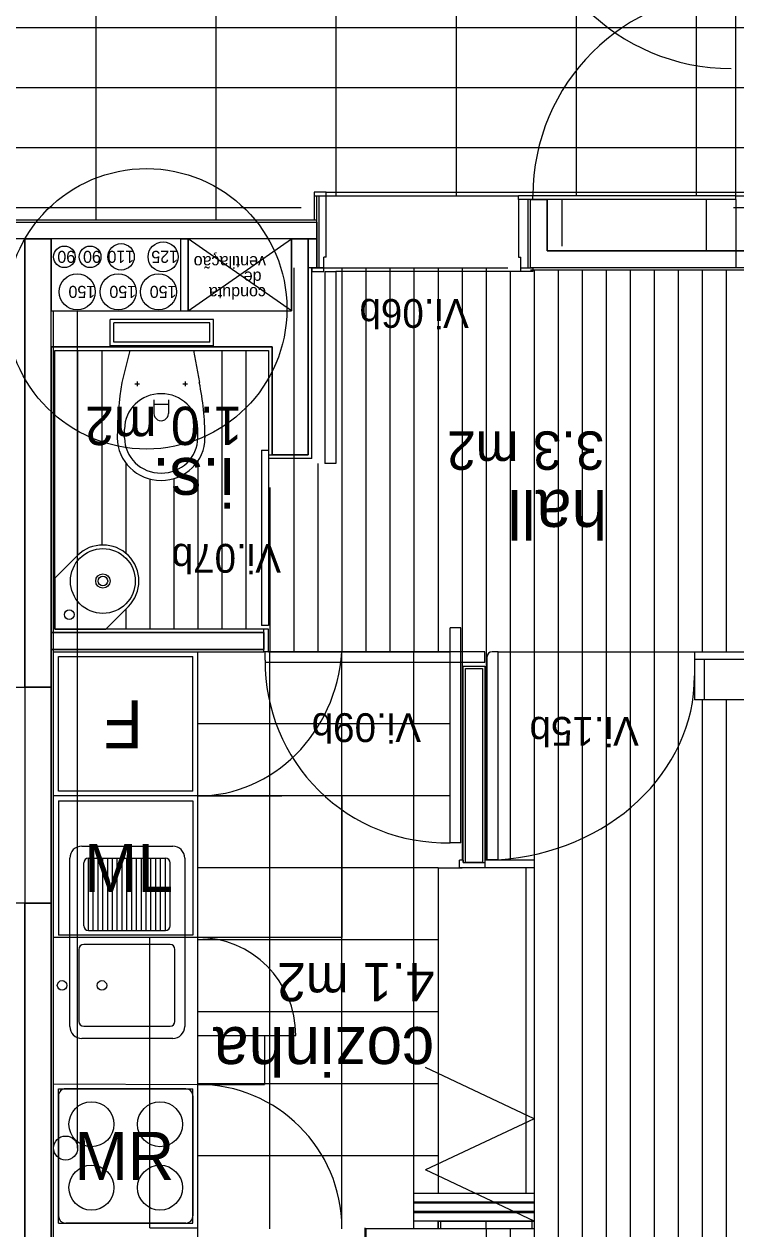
# Model space of a CAD drawing. Extents: x 1248 to 1356, y -443 to -224.
# Drawn here: x 1334.72 to 1337.68, y -244.43 to -239.41 of the extents above; entities that cross this region are included whole.
import ezdxf

# ---------------------------------------------------------------- set-up
doc = ezdxf.new("R2010")
doc.units = 0
for name, color, linetype in [('corte', 7, 'Continuous'), ('estereoctomias', 7, 'Continuous'), ('ind-pormenores', 7, 'Continuous'), ('Level 1', 7, 'Continuous'), ('Level 10', 7, 'Continuous'), ('Level 11', 7, 'Continuous'), ('Level 13', 7, 'Continuous'), ('Level 2', 7, 'Continuous'), ('Level 3', 7, 'Continuous'), ('Level 31', 7, 'Continuous'), ('Level 4', 7, 'Continuous'), ('Level 40', 7, 'Continuous'), ('Level 41', 7, 'Continuous'), ('Level 60', 7, 'Continuous'), ('mob-fixo', 7, 'Continuous'), ('revestimentos', 7, 'Continuous')]:
    doc.layers.add(name, color=color, linetype=linetype)

msp = doc.modelspace()

# ---------------------------------------------------------------- linework, layer by layer
at = {"layer": 'corte'}
for p, q in [((1335.8333, -240.304), (1332.3825, -240.304)), ((1335.3733, -240.604), (1335.3733, -240.304)), ((1335.4033, -240.604), (1335.4033, -240.304)), ((1335.8333, -240.304), (1335.8333, -240.604)), ((1335.9383, -240.304), (1335.9033, -240.304)), ((1337.7283, -240.354), (1336.8983, -240.354)), ((1340.0033, -240.424), (1336.8283, -240.424)), ((1334.8333, -240.754), (1335.7533, -240.754)), ((1336.5483, -242.892), (1336.5483, -242.902)), ((1336.6383, -242.892), (1336.6383, -242.924))]:
    msp.add_line(p, q, dxfattribs=at)
msp.add_lwpolyline([(1334.8325, -243.0713), (1334.6025, -243.0713), (1334.6025, -242.1713), (1334.8325, -242.1713)], close=True, dxfattribs=at)
at = {"layer": 'estereoctomias'}
msp.add_line((1335.9783, -240.124), (1336.7783, -240.124), dxfattribs=at)
for points in [[(1340.0033, -242.1713), (1340.0033, -240.424), (1336.8283, -240.424), (1336.8283, -240.139), (1336.8983, -240.139), (1336.8983, -240.354), (1340.0733, -240.354), (1340.0733, -242.1717)], [(1335.9383, -240.234), (1335.9383, -240.304), (1332.3825, -240.304), (1332.3825, -240.354), (1332.3125, -240.354), (1332.3125, -240.234)], [(1335.9033, -240.304), (1335.9033, -241.204), (1335.7533, -241.204), (1335.7533, -240.754), (1334.8333, -240.754), (1334.8333, -242.1713), (1334.7233, -242.1713), (1334.7233, -240.304), (1334.8333, -240.304), (1334.8333, -240.604), (1335.3733, -240.604), (1335.3733, -240.304), (1335.4033, -240.304), (1335.4033, -240.604), (1335.8333, -240.604), (1335.8333, -240.304)], [(1335.9383, -240.424), (1335.9033, -240.424), (1335.9033, -240.314), (1335.9033, -240.304), (1335.9383, -240.304), (1335.9383, -240.314)], [(1335.7183, -241.944), (1335.7183, -242.014), (1334.8333, -242.014), (1334.8333, -241.944)], [(1336.6283, -242.094), (1336.6283, -242.902), (1336.5583, -242.902), (1336.5583, -242.094)], [(1334.8325, -245.8713), (1334.7233, -245.8713), (1334.7233, -243.0713), (1334.8333, -243.0713), (1334.8333, -245.8713)], [(1336.8433, -244.3959), (1336.8433, -244.4279), (1336.4433, -244.4279), (1336.4433, -244.3959)]]:
    msp.add_lwpolyline(points, close=True, dxfattribs=at)
at = {"layer": 'ind-pormenores'}
msp.add_circle((1335.2301, -240.5951), 0.5842, dxfattribs=at)
at = {"layer": 'Level 1'}
for p, q in [((1336.8983, -240.139), (1336.8283, -240.139)), ((1336.8283, -240.424), (1336.8283, -240.139)), ((1336.8983, -240.354), (1336.8983, -240.139)), ((1332.3125, -240.234), (1335.9383, -240.234)), ((1335.9383, -240.424), (1335.9383, -240.234)), ((1334.7233, -240.304), (1334.7233, -246.734)), ((1334.8333, -241.934), (1334.8333, -240.304)), ((1335.9033, -241.204), (1335.9033, -240.304)), ((1335.9383, -240.424), (1335.9033, -240.424)), ((1334.8333, -240.604), (1335.8333, -240.604)), ((1335.7533, -240.754), (1335.7533, -241.204)), ((1335.7383, -241.204), (1335.9033, -241.204)), ((1334.8333, -246.584), (1334.8333, -241.934)), ((1335.7183, -241.944), (1334.8333, -241.944)), ((1335.7183, -242.024), (1335.7183, -241.929)), ((1334.8333, -242.014), (1335.7183, -242.014)), ((1336.5583, -242.902), (1336.5583, -242.094)), ((1336.5583, -242.094), (1336.6283, -242.094)), ((1336.6283, -242.094), (1336.6283, -242.902)), ((1336.5483, -242.892), (1336.5333, -242.892)), ((1336.5333, -242.924), (1336.5333, -242.892)), ((1336.5483, -242.902), (1336.6383, -242.902)), ((1336.8433, -242.892), (1336.6383, -242.892)), ((1336.8433, -242.892), (1336.8433, -242.924)), ((1336.8433, -242.924), (1336.5333, -242.924)), ((1336.4433, -244.3959), (1336.4433, -244.424)), ((1336.8433, -244.3959), (1336.4433, -244.3959)), ((1336.4433, -244.3959), (1336.4433, -244.4279)), ((1336.4533, -244.3959), (1336.4533, -244.4279)), ((1336.6433, -244.4279), (1336.6433, -244.3959)), ((1336.8333, -244.3959), (1336.8333, -244.4279)), ((1336.8433, -244.3959), (1336.8433, -244.4279)), ((1336.8433, -244.4279), (1336.6433, -244.4279))]:
    msp.add_line(p, q, dxfattribs=at)
at = {"layer": 'Level 10'}
for p, q in [((1335.0183, -238.624), (1335.0183, -240.224)), ((1335.5183, -238.624), (1335.5183, -240.224)), ((1336.0183, -238.724), (1336.0183, -240.124)), ((1336.5183, -238.724), (1336.5183, -240.124)), ((1337.0183, -238.724), (1337.0183, -240.124)), ((1337.5183, -238.724), (1337.5183, -240.124)), ((1347.9933, -239.424), (1315.7633, -239.424)), ((1347.9933, -239.674), (1315.7633, -239.674)), ((1347.9933, -239.924), (1315.7633, -239.924)), ((1335.8733, -240.174), (1332.2725, -240.174)), ((1341.274, -240.174), (1337.6733, -240.174)), ((1335.8433, -240.424), (1335.8433, -242.024)), ((1335.9133, -240.424), (1336.7333, -240.424)), ((1336.0433, -240.424), (1336.0433, -242.024)), ((1336.1433, -240.424), (1336.1433, -242.024)), ((1336.2433, -240.424), (1336.2433, -242.024)), ((1336.3433, -240.424), (1336.3433, -242.024)), ((1336.4433, -240.424), (1336.4433, -242.024)), ((1336.5433, -240.424), (1336.5433, -242.892)), ((1336.6433, -240.424), (1336.6433, -242.892)), ((1336.7433, -240.439), (1336.7433, -242.892)), ((1336.8433, -240.434), (1336.8433, -242.892)), ((1336.9433, -240.434), (1336.9433, -246.574)), ((1337.0433, -240.434), (1337.0433, -246.574)), ((1337.1433, -240.434), (1337.1433, -246.574)), ((1337.2433, -240.434), (1337.2433, -246.574)), ((1337.3433, -240.434), (1337.3433, -246.574)), ((1337.4433, -240.434), (1337.4433, -246.574)), ((1337.5433, -240.434), (1337.5433, -242.024)), ((1337.6433, -240.434), (1337.6433, -242.024)), ((1334.9433, -240.769), (1334.9433, -241.6218)), ((1335.0433, -240.769), (1335.0433, -241.579)), ((1335.5433, -240.769), (1335.5433, -241.929)), ((1335.6433, -240.769), (1335.6433, -241.929)), ((1335.1433, -241.2366), (1335.1433, -241.6129)), ((1335.4433, -241.2297), (1335.4433, -241.929)), ((1335.9433, -241.239), (1335.9433, -242.024)), ((1335.2433, -241.3035), (1335.2433, -241.929)), ((1335.3433, -241.3022), (1335.3433, -241.929)), ((1335.7433, -241.339), (1335.7433, -242.024)), ((1335.1433, -241.8461), (1335.1433, -241.929)), ((1335.7383, -242.024), (1336.4933, -242.024)), ((1335.7433, -244.428), (1335.7433, -242.024)), ((1336.0433, -244.428), (1336.0433, -242.024)), ((1336.3433, -244.428), (1336.3433, -242.024)), ((1337.5433, -242.224), (1337.5433, -246.574)), ((1337.6433, -242.224), (1337.6433, -246.574)), ((1336.4933, -242.324), (1335.4433, -242.324)), ((1336.4933, -242.624), (1335.4433, -242.624)), ((1336.4933, -242.624), (1335.4433, -242.624)), ((1336.4433, -242.924), (1335.4433, -242.924)), ((1336.4433, -243.224), (1335.4433, -243.224)), ((1336.4433, -243.224), (1335.4433, -243.224)), ((1336.4433, -243.524), (1335.4433, -243.524)), ((1336.4433, -243.824), (1335.4433, -243.824)), ((1336.4433, -244.124), (1335.4433, -244.124)), ((1336.7433, -244.4279), (1336.7433, -246.574)), ((1336.8433, -244.4279), (1336.8433, -246.574))]:
    msp.add_line(p, q, dxfattribs=at)
at = {"layer": 'Level 11'}
for p, q in [((1335.0783, -240.749), (1335.0783, -240.639)), ((1335.5083, -240.639), (1335.0783, -240.639)), ((1335.4933, -240.654), (1335.0933, -240.654)), ((1335.0933, -240.734), (1335.0933, -240.654)), ((1335.4933, -240.734), (1335.4933, -240.654)), ((1335.5083, -240.749), (1335.5083, -240.639)), ((1335.5083, -240.749), (1335.0783, -240.749)), ((1335.4933, -240.734), (1335.0933, -240.734)), ((1335.1609, -240.769), (1335.1269, -240.9017)), ((1335.1609, -240.769), (1335.4256, -240.769)), ((1335.4256, -240.769), (1335.4498, -240.9017)), ((1335.1808, -240.9079), (1335.2008, -240.9079)), ((1335.1908, -240.8979), (1335.1908, -240.9179)), ((1335.3808, -240.9079), (1335.4008, -240.9079)), ((1335.3908, -240.8979), (1335.3908, -240.9179)), ((1335.2608, -240.9742), (1335.2608, -241.0313)), ((1335.2608, -240.9919), (1335.3208, -240.9919)), ((1335.3208, -240.9742), (1335.3208, -241.0314)), ((1335.1383, -241.1322), (1335.1383, -241.0961)), ((1335.4433, -241.1322), (1335.4433, -241.0961)), ((1335.1083, -241.1288), (1335.1083, -241.1325)), ((1335.4733, -241.1288), (1335.4733, -241.1325)), ((1334.9422, -241.6229), (1334.8483, -241.7168)), ((1334.8483, -241.7168), (1334.8483, -241.929)), ((1335.1543, -241.835), (1335.0604, -241.929)), ((1334.8483, -241.929), (1335.0604, -241.929)), ((1334.8633, -242.604), (1334.8633, -242.044)), ((1334.8633, -242.044), (1335.4233, -242.044)), ((1335.4233, -242.604), (1335.4233, -242.044)), ((1335.4233, -242.604), (1334.8633, -242.604)), ((1334.9684, -243.1651), (1334.9684, -242.9035)), ((1334.9884, -242.8835), (1335.3084, -242.8835)), ((1334.9884, -243.1851), (1334.9884, -242.8835)), ((1335.0084, -243.1851), (1335.0084, -242.8835)), ((1335.0284, -243.1851), (1335.0284, -242.8835)), ((1335.0484, -243.1851), (1335.0484, -242.8835)), ((1335.0684, -243.1851), (1335.0684, -242.8835)), ((1335.0884, -243.1851), (1335.0884, -242.8835)), ((1335.1084, -243.1851), (1335.1084, -242.8835)), ((1335.1284, -243.1851), (1335.1284, -242.8835)), ((1335.1484, -243.1851), (1335.1484, -242.8835)), ((1335.1684, -243.1851), (1335.1684, -242.8835)), ((1335.1884, -243.1851), (1335.1884, -242.8835)), ((1335.2084, -243.1851), (1335.2084, -242.8835)), ((1335.2284, -243.1851), (1335.2284, -242.8835)), ((1335.2484, -243.1851), (1335.2484, -242.8835)), ((1335.2684, -243.1851), (1335.2684, -242.8835)), ((1335.2884, -243.1851), (1335.2884, -242.8835)), ((1335.3084, -243.1851), (1335.3084, -242.8835)), ((1335.3284, -243.1651), (1335.3284, -242.9035)), ((1334.9884, -243.1851), (1335.3084, -243.1851)), ((1334.9484, -243.2635), (1334.9484, -243.5635)), ((1335.3284, -243.2435), (1334.9684, -243.2435)), ((1335.3484, -243.5635), (1335.3484, -243.2635)), ((1334.9684, -243.5835), (1335.3284, -243.5835)), ((1335.3934, -243.844), (1334.8934, -243.844)), ((1334.8634, -243.874), (1334.8634, -244.374)), ((1335.4234, -243.874), (1335.4234, -244.374)), ((1335.3934, -244.404), (1334.8934, -244.404))]:
    msp.add_line(p, q, dxfattribs=at)
for points in [[(1334.9606, -242.8333), (1335.339, -242.8333)], [(1334.9106, -243.5847), (1334.9106, -242.8833)], [(1335.389, -242.8833), (1335.389, -243.5847)], [(1335.339, -243.6347), (1334.9606, -243.6347)]]:
    msp.add_lwpolyline(points, dxfattribs=at)
for centre, radius in [((1335.0483, -241.729), 0.135), ((1335.0483, -241.729), 0.03), ((1335.0483, -241.729), 0.02), ((1334.9083, -241.869), 0.02), ((1334.8784, -243.4135), 0.0199), ((1335.0444, -243.4135), 0.0199), ((1335.0007, -243.9919), 0.0936), ((1335.286, -243.9919), 0.0936), ((1335.0007, -244.2561), 0.0936), ((1335.286, -244.2561), 0.0936)]:
    msp.add_circle(centre, radius, dxfattribs=at)
for centre, radius, start, end in [((1335.2908, -241.0312), 0.03, 179.9995, 0.0013), ((1335.0483, -241.729), 0.15, 315, 134.9998), ((1334.9605, -242.8833), 0.05, 90, 180), ((1335.3389, -242.8833), 0.05, 0, 90), ((1334.9884, -242.9035), 0.02, 90, 180), ((1335.3084, -242.9035), 0.02, 0, 90), ((1334.9884, -243.1651), 0.02, 180, 270), ((1335.3084, -243.1651), 0.02, 270, 0), ((1334.9684, -243.2635), 0.02, 90, 180), ((1335.3284, -243.2635), 0.02, 0, 90), ((1334.9684, -243.5635), 0.02, 180, 270), ((1335.3284, -243.5635), 0.02, 270, 0), ((1334.9605, -243.5847), 0.05, 180, 270), ((1335.3389, -243.5847), 0.05, 270, 0), ((1334.8934, -243.874), 0.03, 89.9999, 180.0002), ((1335.3934, -243.874), 0.03, 0.0001, 90.0001), ((1334.8934, -244.374), 0.03, 180.0002, 270), ((1335.3934, -244.374), 0.03, 270.0001, 0)]:
    msp.add_arc(centre, radius, start, end, dxfattribs=at)
for centre, major_axis, ratio, start_param, end_param in [((1336.5079, -241.1288), (0, -1.4), 0.999692, 4.549473, 4.712392), ((1333.695, -241.1288), (1.7783, 0), 0.787256, 6.283184, 6.446103), ((1335.2908, -241.0961), (0.1525, 0), 0.967187, 0.000003, 3.14159), ((1335.2908, -241.1322), (0.1825, 0), 0.972581, 3.141597, 6.283184), ((1335.2908, -241.1322), (0.1525, 0), 0.967187, 3.141597, 6.283184)]:
    msp.add_ellipse(centre, major_axis=major_axis, ratio=ratio, start_param=start_param, end_param=end_param, dxfattribs=at)
at = {"layer": 'Level 13'}
for p, q in [((1335.9783, -240.109), (1335.9283, -240.109)), ((1335.9283, -240.109), (1335.9283, -240.224)), ((1335.9283, -240.124), (1335.9783, -240.124)), ((1335.9383, -240.244), (1335.9383, -240.124)), ((1335.9483, -240.424), (1335.9483, -240.124)), ((1335.9783, -240.124), (1335.9783, -240.109)), ((1335.9783, -240.38), (1335.9783, -240.124)), ((1336.7783, -240.139), (1336.7783, -240.124)), ((1336.8383, -240.124), (1336.7783, -240.124)), ((1336.7783, -240.139), (1336.7783, -240.38)), ((1337.6833, -240.139), (1336.7783, -240.139)), ((1337.6833, -240.124), (1336.8183, -240.124)), ((1337.6833, -240.124), (1336.8183, -240.124)), ((1336.8183, -240.424), (1336.8183, -240.139)), ((1337.6833, -240.124), (1336.8383, -240.124)), ((1336.8383, -240.139), (1336.8383, -240.124)), ((1337.6833, -240.124), (1337.6833, -240.109)), ((1337.6833, -240.109), (1337.7283, -240.109)), ((1337.6833, -240.139), (1337.6833, -240.124)), ((1337.6833, -240.124), (1337.7283, -240.124)), ((1337.6833, -240.139), (1337.6833, -240.354)), ((1335.9483, -240.424), (1335.9483, -240.224)), ((1335.9783, -240.38), (1335.9683, -240.38)), ((1335.9683, -240.424), (1335.9683, -240.38)), ((1336.7783, -240.38), (1336.7883, -240.38)), ((1336.7883, -240.424), (1336.7883, -240.38)), ((1335.9183, -241.219), (1335.9183, -240.424)), ((1335.9723, -240.439), (1335.9723, -241.239)), ((1335.9733, -240.439), (1336.0173, -240.439)), ((1336.0173, -240.439), (1336.0173, -241.239)), ((1335.7083, -241.184), (1335.7083, -241.914)), ((1335.7083, -241.184), (1335.7383, -241.184)), ((1335.7383, -241.184), (1335.7383, -241.914)), ((1335.9183, -241.219), (1335.7383, -241.219)), ((1336.0173, -241.239), (1335.9723, -241.239)), ((1335.7383, -241.914), (1335.7083, -241.914)), ((1336.5383, -241.924), (1336.4933, -241.924)), ((1336.4933, -242.819), (1336.4933, -241.924)), ((1336.5383, -242.819), (1336.5383, -241.924)), ((1336.5383, -242.819), (1336.5383, -241.924)), ((1336.5383, -242.819), (1336.5383, -241.924)), ((1335.4433, -245.121), (1335.4433, -242.024)), ((1336.6483, -242.8898), (1336.6483, -242.044)), ((1336.6933, -242.024), (1336.6683, -242.024)), ((1336.6933, -242.8898), (1336.6933, -242.024)), ((1337.5113, -242.024), (1337.5113, -242.224)), ((1337.5113, -242.024), (1339.9933, -242.024)), ((1337.5113, -242.024), (1339.9933, -242.024)), ((1337.5113, -242.054), (1339.9933, -242.054)), ((1337.5513, -242.054), (1337.5513, -242.224)), ((1339.9933, -242.224), (1337.5113, -242.224)), ((1335.4433, -242.624), (1334.8433, -242.624)), ((1336.5383, -242.819), (1336.4933, -242.819)), ((1336.6933, -242.8898), (1336.6483, -242.8898)), ((1336.8433, -244.2809), (1336.3433, -244.2809)), ((1336.3433, -244.3159), (1336.3433, -244.2809)), ((1336.8433, -244.3159), (1336.3433, -244.3159)), ((1336.8433, -244.3209), (1336.3433, -244.3209)), ((1336.3433, -244.3559), (1336.3433, -244.3209)), ((1336.8433, -244.3559), (1336.3433, -244.3559)), ((1336.8433, -244.3609), (1336.3433, -244.3609)), ((1336.3433, -244.3959), (1336.3433, -244.3609)), ((1336.4433, -244.3959), (1336.3433, -244.3959))]:
    msp.add_line(p, q, dxfattribs=at)
for points in [[(1335.9683, -240.424), (1335.9183, -240.424), (1335.9183, -240.439), (1335.9683, -240.439)], [(1336.8383, -240.439), (1336.7883, -240.439), (1336.7883, -240.424), (1336.8383, -240.424)]]:
    msp.add_lwpolyline(points, close=True, dxfattribs=at)
msp.add_arc((1336.6683, -242.044), 0.02, 90, 180, dxfattribs=at)
at = {"layer": 'Level 2'}
for p, q in [((1336.4433, -242.924), (1336.4433, -244.2809)), ((1336.4433, -242.924), (1336.5433, -242.924)), ((1336.8433, -242.924), (1336.8433, -244.3959)), ((1336.4433, -244.3159), (1336.4433, -244.3209)), ((1336.4433, -244.3559), (1336.4433, -244.3609))]:
    msp.add_line(p, q, dxfattribs=at)
at = {"layer": 'Level 3'}
for p, q in [((1335.4433, -243.214), (1334.8433, -243.214)), ((1335.2433, -244.424), (1335.2433, -243.214)), ((1335.2433, -244.424), (1335.4433, -244.424))]:
    msp.add_line(p, q, dxfattribs=at)
at = {"layer": 'Level 31'}
for p, q in [((1335.7383, -241.929), (1335.7183, -241.929)), ((1335.7383, -242.024), (1335.7383, -241.929)), ((1335.7383, -242.024), (1335.7183, -242.024))]:
    msp.add_line(p, q, dxfattribs=at)
at = {"layer": 'Level 4'}
for p, q in [((1337.6833, -240.124), (1337.6833, -239.279)), ((1335.9783, -240.109), (1337.6833, -240.109)), ((1336.9608, -240.334), (1336.9608, -240.139)), ((1337.5608, -240.354), (1337.5608, -240.139)), ((1337.6833, -240.354), (1337.6833, -240.424)), ((1336.7883, -240.439), (1336.0173, -240.439)), ((1334.8433, -242.024), (1335.4433, -242.024)), ((1335.7233, -242.059), (1335.7233, -242.024)), ((1336.6383, -242.024), (1335.7233, -242.024)), ((1336.6383, -242.069), (1336.6383, -242.024)), ((1336.6933, -242.024), (1337.5113, -242.024)), ((1336.6383, -242.069), (1335.7233, -242.069)), ((1334.8633, -242.644), (1334.8633, -243.204)), ((1334.8633, -242.644), (1335.4233, -242.644)), ((1335.4233, -242.644), (1335.4233, -243.204)), ((1335.4433, -242.624), (1335.7933, -242.624)), ((1335.4433, -242.624), (1335.7933, -242.624)), ((1336.0433, -242.624), (1336.0433, -243.214)), ((1336.8083, -242.924), (1336.8083, -244.2809)), ((1335.4233, -243.204), (1334.8633, -243.204)), ((1336.0433, -243.214), (1335.4433, -243.214)), ((1335.4433, -243.622), (1335.8513, -243.622)), ((1335.7207, -243.622), (1335.7207, -243.8263)), ((1336.8433, -243.9691), (1336.3911, -243.7557)), ((1334.8433, -243.824), (1335.4433, -243.8263)), ((1334.8633, -243.844), (1335.4233, -243.844)), ((1334.8633, -244.404), (1334.8633, -243.844)), ((1335.4233, -244.404), (1335.4233, -243.844)), ((1335.4433, -243.8263), (1335.7207, -243.8263)), ((1336.8433, -243.9691), (1336.3911, -244.1825)), ((1336.8433, -244.3959), (1336.3911, -244.1825)), ((1334.8633, -244.404), (1335.4233, -244.404))]:
    msp.add_line(p, q, dxfattribs=at)
for centre, radius, start, end in [((1337.6833, -240.124), 0.845, 90, 180), ((1336.4775, -242.0652), 0.7542, 179.5297, 271.1986), ((1335.4433, -243.622), 0.408, 0, 90), ((1335.4433, -244.4263), 0.6, 0.2225, 90), ((1335.4433, -244.424), 0.697, 270, 0)]:
    msp.add_arc(centre, radius, start, end, dxfattribs=at)
for centre, major_axis, ratio, start_param, end_param in [((1337.6633, -238.739), (-0.8551, 0), 0.999998, 0, 1.570796), ((1335.4433, -241.9731), (0, -0.6509), 0.924693, 0, 1.492592), ((1336.6279, -242.124), (-0.8834, 0), 0.869287, 1.644887, 3.141577)]:
    msp.add_ellipse(centre, major_axis=major_axis, ratio=ratio, start_param=start_param, end_param=end_param, dxfattribs=at)
at = {"layer": 'Level 41'}
for p, q in [((1335.8333, -240.604), (1335.4033, -240.304)), ((1335.4033, -240.604), (1335.8333, -240.304))]:
    msp.add_line(p, q, dxfattribs=at)
for centre, radius in [((1334.8881, -240.3785), 0.045), ((1334.9951, -240.3785), 0.045), ((1335.1241, -240.3785), 0.055), ((1335.2989, -240.3785), 0.0625), ((1334.9416, -240.5244), 0.075), ((1335.1118, -240.5244), 0.075), ((1335.2798, -240.5244), 0.075)]:
    msp.add_circle(centre, radius, dxfattribs=at)
at = {"layer": 'mob-fixo'}
for p, q in [((1334.8433, -244.091), (1334.8433, -240.604)), ((1334.9433, -244.091), (1334.9433, -240.604))]:
    msp.add_line(p, q, dxfattribs=at)
msp.add_circle((1334.8933, -244.091), 0.05, dxfattribs=at)
at = {"layer": 'revestimentos'}
for p, q in [((1332.3125, -240.224), (1335.9383, -240.224)), ((1339.9933, -240.434), (1336.8283, -240.434)), ((1334.8483, -241.929), (1334.8483, -240.769)), ((1334.8483, -240.769), (1335.7383, -240.769)), ((1335.7383, -240.769), (1335.7383, -241.204)), ((1335.7183, -241.929), (1334.8483, -241.929)), ((1334.8433, -246.574), (1334.8433, -242.024)), ((1334.8433, -242.024), (1335.7183, -242.024)), ((1336.5483, -242.902), (1336.5483, -242.084)), ((1336.5483, -242.084), (1336.6383, -242.084)), ((1336.6383, -242.084), (1336.6383, -242.892)), ((1336.6433, -244.4279), (1336.1433, -244.4279)), ((1336.1433, -244.4279), (1336.1433, -244.5179)), ((1336.6433, -244.4279), (1336.6433, -244.5179))]:
    msp.add_line(p, q, dxfattribs=at)

# ---------------------------------------------------------------- texts
at = {"layer": 'Level 11'}
msp.add_text('F', height=0.2, rotation=180, dxfattribs=at).set_placement((1335.2148, -242.2263))
for s, p in [('ML', (1334.9693, -243.024)), ('MR', (1334.9296, -244.224))]:
    msp.add_text(s, height=0.2, dxfattribs=at).set_placement(p)
at = {"layer": 'Level 40'}
for s, p in [('Vi.06b', (1336.5715, -240.5543)), ('Vi.07b', (1335.7898, -241.5742)), ('Vi.09b', (1336.3727, -242.2797)), ('Vi.15b', (1337.2793, -242.295))]:
    msp.add_text(s, height=0.12, rotation=180, dxfattribs=at).set_placement(p)
at = {"layer": 'Level 41'}
for s, p in [('90', (1334.9331, -240.3535)), ('90', (1335.0401, -240.3535)), ('110', (1335.1791, -240.3535)), ('125', (1335.3614, -240.3535)), ('ventilação ', (1335.7273, -240.3755)), (' de ', (1335.7273, -240.4399)), ('150', (1335.0166, -240.4994)), ('150', (1335.1868, -240.4994)), ('150', (1335.3548, -240.4994)), ('conduta', (1335.7273, -240.5044))]:
    msp.add_text(s, height=0.05, rotation=180, dxfattribs=at).set_placement(p)
at = {"layer": 'Level 60'}
for s, height, p in [('1.0 m2', 0.16, (1335.6288, -241.0026)), ('3.3 m2', 0.16, (1337.1356, -241.1056)), ('i.s.', 0.2, (1335.5949, -241.2167)), ('hall', 0.2, (1337.1479, -241.3499)), ('4.1 m2', 0.16, (1336.4281, -243.3196)), ('cozinha', 0.2, (1336.4281, -243.5874))]:
    msp.add_text(s, height=height, rotation=180, dxfattribs=at).set_placement(p)

doc.saveas('drawing.dxf')
